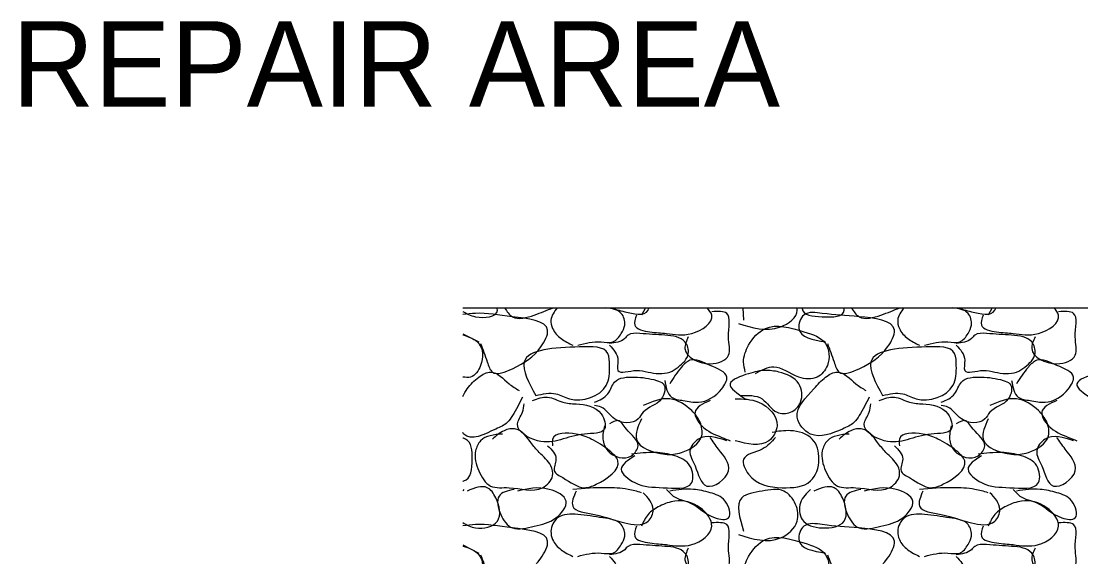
# Model space of a CAD drawing. Extents: x 2.92 to 10.05, y 1.3 to 10.63.
# Drawn here: x 3.291 to 4.036, y 6.374 to 6.75 of the extents above; entities that cross this region are included whole.
import ezdxf

# ---------------------------------------------------------------- set-up
doc = ezdxf.new("R2010")
doc.units = 0
for name, color, linetype in [('DETL-LINE', 7, 'Continuous'), ('DETL-NOTE', 7, 'Continuous'), ('DETL-PATT', 7, 'Continuous')]:
    doc.layers.add(name, color=color, linetype=linetype)

msp = doc.modelspace()

# ---------------------------------------------------------------- linework, layer by layer
at = {"layer": 'DETL-LINE'}
msp.add_line((3.60141, 6.54902), (7.87612, 6.54902), dxfattribs=at)
at = {"layer": 'DETL-PATT'}
for p, q in [((3.7298, 6.54902), (3.7269, 6.54392)), ((3.79824, 6.54902), (3.79867, 6.54039)), ((3.97333, 6.54902), (3.97043, 6.54392)), ((3.60141, 6.53078), (3.61278, 6.5251)), ((3.6022, 6.42157), (3.60141, 6.42051)), ((3.60141, 6.38255), (3.61278, 6.37686))]:
    msp.add_line(p, q, dxfattribs=at)
for points in [[(3.60141, 6.54651), (3.61043, 6.54275), (3.62573, 6.54745), (3.62561, 6.54902)], [(3.61396, 6.52392), (3.61867, 6.51098), (3.6222, 6.50392), (3.63631, 6.50627), (3.65631, 6.52157), (3.66102, 6.53333), (3.63631, 6.54275), (3.61043, 6.5451), (3.60141, 6.54427)], [(3.63082, 6.54902), (3.63631, 6.54275), (3.65161, 6.54392), (3.66486, 6.54902)], [(3.66769, 6.54902), (3.66337, 6.54039), (3.66455, 6.53451), (3.67043, 6.52745), (3.67867, 6.52275)], [(3.6822, 6.52275), (3.69867, 6.5251), (3.7069, 6.5251), (3.71278, 6.53098), (3.71514, 6.53686), (3.71278, 6.5451), (3.702, 6.54902)], [(3.70525, 6.54902), (3.71514, 6.54627), (3.73161, 6.54745), (3.73227, 6.54902)], [(3.72337, 6.54392), (3.7222, 6.53686), (3.73278, 6.53216), (3.74455, 6.53098), (3.7622, 6.53098), (3.77631, 6.54392), (3.77306, 6.54902)], [(3.75984, 6.52863), (3.75749, 6.52039), (3.77514, 6.5098), (3.78808, 6.51569), (3.78808, 6.52863), (3.7869, 6.5451), (3.77631, 6.54627)], [(3.79514, 6.53804), (3.82455, 6.53569), (3.83631, 6.54745), (3.83616, 6.54902)], [(3.85749, 6.52392), (3.8622, 6.51098), (3.86573, 6.50392), (3.87984, 6.50627), (3.89984, 6.52157), (3.90455, 6.53333), (3.87984, 6.54275), (3.85396, 6.5451), (3.84102, 6.54392), (3.83749, 6.53451), (3.85631, 6.5251)], [(3.8398, 6.54902), (3.83984, 6.54863), (3.85396, 6.54275), (3.86925, 6.54745), (3.86914, 6.54902)], [(3.87435, 6.54902), (3.87984, 6.54275), (3.89514, 6.54392), (3.90839, 6.54902)], [(3.91122, 6.54902), (3.9069, 6.54039), (3.90808, 6.53451), (3.91396, 6.52745), (3.9222, 6.52275)], [(3.92573, 6.52275), (3.9422, 6.5251), (3.95043, 6.5251), (3.95631, 6.53098), (3.95867, 6.53686), (3.95631, 6.5451), (3.94553, 6.54902)], [(3.94878, 6.54902), (3.95867, 6.54627), (3.97514, 6.54745), (3.9758, 6.54902)], [(3.9669, 6.54392), (3.96573, 6.53686), (3.97631, 6.53216), (3.98808, 6.53098), (4.00573, 6.53098), (4.01984, 6.54392), (4.01659, 6.54902)], [(4.00337, 6.52863), (4.00102, 6.52039), (4.01867, 6.5098), (4.03161, 6.51569), (4.03161, 6.52863), (4.03043, 6.5451), (4.01984, 6.54627)], [(3.79984, 6.50392), (3.79867, 6.51098), (3.8022, 6.52275), (3.81396, 6.53451), (3.84102, 6.53216), (3.85631, 6.52392), (3.85749, 6.50863), (3.85043, 6.50039), (3.83749, 6.50039), (3.81984, 6.50745), (3.8069, 6.50275)], [(3.60141, 6.53004), (3.61278, 6.52392), (3.61396, 6.50863), (3.6069, 6.50039), (3.60141, 6.50039)], [(3.70455, 6.52275), (3.71043, 6.51216), (3.71043, 6.5051), (3.72337, 6.5051), (3.73161, 6.50392), (3.7469, 6.50392), (3.75278, 6.50745), (3.75984, 6.51686), (3.75749, 6.5251), (3.75161, 6.52863), (3.74337, 6.5298), (3.72573, 6.53098), (3.71749, 6.5298), (3.71514, 6.52745), (3.70455, 6.52392)], [(3.94808, 6.52275), (3.95396, 6.51216), (3.95396, 6.5051), (3.9669, 6.5051), (3.97514, 6.50392), (3.99043, 6.50392), (3.99631, 6.50745), (4.00337, 6.51686), (4.00102, 6.5251), (3.99514, 6.52863), (3.9869, 6.5298), (3.96925, 6.53098), (3.96102, 6.5298), (3.95867, 6.52745), (3.94808, 6.52392)], [(3.65278, 6.48745), (3.64455, 6.51098), (3.68337, 6.52157), (3.70337, 6.51686), (3.70455, 6.50863), (3.7022, 6.49451), (3.67631, 6.4851), (3.6669, 6.48863), (3.65278, 6.48745)], [(3.89631, 6.48745), (3.88808, 6.51098), (3.9269, 6.52157), (3.9469, 6.51686), (3.94808, 6.50863), (3.94573, 6.49451), (3.91984, 6.4851), (3.91043, 6.48863), (3.89631, 6.48745)], [(3.74337, 6.49804), (3.74808, 6.48627), (3.75631, 6.48392), (3.7669, 6.48275), (3.78337, 6.49216), (3.7869, 6.50039), (3.77514, 6.50863), (3.76102, 6.51216), (3.75514, 6.50745), (3.7469, 6.49569)], [(3.9869, 6.49804), (3.99161, 6.48627), (3.99984, 6.48392), (4.01043, 6.48275), (4.0269, 6.49216), (4.03043, 6.50039), (4.01867, 6.50863), (4.00455, 6.51216), (3.99867, 6.50745), (3.99043, 6.49569)], [(3.79631, 6.48745), (3.81161, 6.4851), (3.8222, 6.47569), (3.83161, 6.47569), (3.83867, 6.48275), (3.83749, 6.49569), (3.82337, 6.50392), (3.81396, 6.5051), (3.8022, 6.50275), (3.78925, 6.49569), (3.79984, 6.4851)], [(4.03984, 6.48745), (4.05514, 6.4851), (4.06573, 6.47569), (4.07514, 6.47569), (4.0822, 6.48275), (4.08102, 6.49569), (4.0669, 6.50392), (4.05749, 6.5051), (4.04573, 6.50275), (4.03278, 6.49569), (4.04337, 6.4851)], [(3.60141, 6.48682), (3.60455, 6.49216), (3.61278, 6.50039), (3.62102, 6.50392), (3.63396, 6.49569), (3.64102, 6.49098)], [(3.69396, 6.48275), (3.70337, 6.48863), (3.70808, 6.49686), (3.7222, 6.50039), (3.73749, 6.49804), (3.7422, 6.49569), (3.74102, 6.4851), (3.72808, 6.47569), (3.72455, 6.47098), (3.70808, 6.47098), (3.69867, 6.47922), (3.69396, 6.48039)], [(3.8869, 6.48627), (3.87984, 6.47333), (3.87631, 6.46863), (3.86808, 6.46392), (3.84573, 6.46039), (3.83631, 6.47216), (3.84808, 6.49216), (3.85631, 6.50039), (3.86455, 6.50392), (3.87749, 6.49569), (3.88455, 6.49098)], [(3.93749, 6.48275), (3.9469, 6.48863), (3.95161, 6.49686), (3.96573, 6.50039), (3.98102, 6.49804), (3.98573, 6.49569), (3.98455, 6.4851), (3.97161, 6.47569), (3.96808, 6.47098), (3.95161, 6.47098), (3.9422, 6.47922), (3.93749, 6.48039)], [(3.64337, 6.48627), (3.63631, 6.47333), (3.63278, 6.46863), (3.62455, 6.46392), (3.6022, 6.46039), (3.60141, 6.46137)], [(3.65043, 6.48392), (3.66102, 6.48627), (3.67161, 6.48275), (3.68102, 6.48157), (3.69867, 6.47451), (3.70102, 6.46392), (3.6869, 6.46039), (3.65396, 6.45569), (3.63984, 6.46745), (3.64337, 6.47569), (3.64455, 6.48157)], [(3.7269, 6.47098), (3.72337, 6.45686), (3.74337, 6.44627), (3.75514, 6.44745), (3.76925, 6.45922), (3.76808, 6.46863), (3.7622, 6.47686), (3.7469, 6.4851), (3.72808, 6.48039)], [(3.77514, 6.48392), (3.76455, 6.47569), (3.76925, 6.46627), (3.78337, 6.45804), (3.78925, 6.45569)], [(3.79278, 6.4851), (3.80925, 6.48275), (3.8222, 6.46627), (3.81631, 6.45569), (3.79278, 6.45569)], [(3.89396, 6.48392), (3.90455, 6.48627), (3.91514, 6.48275), (3.92455, 6.48157), (3.9422, 6.47451), (3.94455, 6.46392), (3.93043, 6.46039), (3.89749, 6.45569), (3.88337, 6.46745), (3.8869, 6.47569), (3.88808, 6.48157)], [(3.97043, 6.47098), (3.9669, 6.45686), (3.9869, 6.44627), (3.99867, 6.44745), (4.01278, 6.45922), (4.01161, 6.46863), (4.00573, 6.47686), (3.99043, 6.4851), (3.97161, 6.48039)], [(4.01867, 6.48392), (4.00808, 6.47569), (4.01278, 6.46627), (4.0269, 6.45804), (4.03278, 6.45569)], [(3.70102, 6.46627), (3.69984, 6.45686), (3.70337, 6.44863), (3.71984, 6.4451), (3.72455, 6.45216), (3.71631, 6.46392), (3.71043, 6.4698), (3.70455, 6.46745)], [(3.94455, 6.46627), (3.94337, 6.45686), (3.9469, 6.44863), (3.96337, 6.4451), (3.96808, 6.45216), (3.95984, 6.46392), (3.95396, 6.4698), (3.94808, 6.46745)], [(3.62925, 6.46039), (3.61396, 6.45569), (3.61043, 6.44863), (3.61278, 6.43451), (3.62102, 6.42392), (3.63396, 6.42275), (3.65749, 6.42275), (3.66455, 6.43098), (3.66337, 6.43804), (3.65514, 6.44745), (3.64925, 6.45451), (3.63867, 6.46392), (3.63043, 6.46275), (3.6222, 6.45686)], [(3.66102, 6.45216), (3.6669, 6.44275), (3.66573, 6.43451), (3.67161, 6.4298), (3.6869, 6.42275), (3.69514, 6.4251), (3.71043, 6.44157), (3.70455, 6.44863), (3.69161, 6.45686), (3.68102, 6.46039), (3.66455, 6.45686), (3.66455, 6.45216)], [(3.7869, 6.45569), (3.7669, 6.45686), (3.76102, 6.44863), (3.76455, 6.43804), (3.77278, 6.42392), (3.78808, 6.43451), (3.78102, 6.4498), (3.77514, 6.45804)], [(3.82102, 6.45804), (3.81161, 6.4498), (3.79867, 6.44275), (3.8022, 6.43216), (3.82573, 6.42275), (3.84573, 6.42745), (3.85161, 6.44275), (3.8469, 6.45686), (3.83161, 6.46275), (3.81867, 6.46157)], [(3.87278, 6.46039), (3.85749, 6.45569), (3.85396, 6.44863), (3.85631, 6.43451), (3.86455, 6.42392), (3.87749, 6.42275), (3.90102, 6.42275), (3.90808, 6.43098), (3.9069, 6.43804), (3.89867, 6.44745), (3.89278, 6.45451), (3.8822, 6.46392), (3.87396, 6.46275), (3.86573, 6.45686)], [(3.90455, 6.45216), (3.91043, 6.44275), (3.90925, 6.43451), (3.91514, 6.4298), (3.93043, 6.42275), (3.93867, 6.4251), (3.95396, 6.44157), (3.94808, 6.44863), (3.93514, 6.45686), (3.92455, 6.46039), (3.90808, 6.45686), (3.90808, 6.45216)], [(4.03043, 6.45569), (4.01043, 6.45686), (4.00455, 6.44863), (4.00808, 6.43804), (4.01631, 6.42392), (4.03161, 6.43451), (4.02455, 6.4498), (4.01867, 6.45804)], [(3.60141, 6.42725), (3.6022, 6.42745), (3.60808, 6.44275), (3.60337, 6.45686), (3.60141, 6.45761)], [(3.7222, 6.4451), (3.71278, 6.43569), (3.7222, 6.42627), (3.7422, 6.42275), (3.7622, 6.42627), (3.76102, 6.43804), (3.75043, 6.4451), (3.73631, 6.44745), (3.71984, 6.44627)], [(3.96573, 6.4451), (3.95631, 6.43569), (3.96573, 6.42627), (3.98573, 6.42275), (4.00573, 6.42627), (4.00455, 6.43804), (3.99396, 6.4451), (3.97984, 6.44745), (3.96337, 6.44627)], [(3.60141, 6.39827), (3.61043, 6.39451), (3.62573, 6.39922), (3.62455, 6.41569), (3.61867, 6.42275), (3.60455, 6.42039)], [(3.63749, 6.42157), (3.6269, 6.41686), (3.62808, 6.40392), (3.63631, 6.39451), (3.65161, 6.39569), (3.6669, 6.40157), (3.67396, 6.41333), (3.6622, 6.42157), (3.63984, 6.42039)], [(3.7269, 6.41922), (3.71749, 6.42157), (3.7022, 6.42275), (3.67867, 6.42157)], [(3.84573, 6.42157), (3.83867, 6.41216), (3.83984, 6.40039), (3.85396, 6.39451), (3.86925, 6.39922), (3.86808, 6.41569), (3.8622, 6.42275), (3.84808, 6.42039)], [(3.88102, 6.42157), (3.87043, 6.41686), (3.87161, 6.40392), (3.87984, 6.39451), (3.89514, 6.39569), (3.91043, 6.40157), (3.91749, 6.41333), (3.90573, 6.42157), (3.88337, 6.42039)], [(3.97043, 6.41922), (3.96102, 6.42157), (3.94573, 6.42275), (3.9222, 6.42157)], [(3.68102, 6.42039), (3.67867, 6.4098), (3.69396, 6.40392), (3.71514, 6.39804), (3.73161, 6.39922), (3.73514, 6.40745), (3.72808, 6.41922)], [(3.74455, 6.42157), (3.74925, 6.41686), (3.76102, 6.41216), (3.77867, 6.40157), (3.78808, 6.40157), (3.78573, 6.41333), (3.77514, 6.41922), (3.76337, 6.42157), (3.7469, 6.42039)], [(3.79514, 6.3898), (3.82455, 6.38745), (3.83631, 6.39922), (3.83514, 6.41098), (3.8269, 6.42039), (3.81161, 6.42039), (3.79749, 6.41569), (3.79867, 6.39216)], [(3.92455, 6.42039), (3.9222, 6.4098), (3.93749, 6.40392), (3.95867, 6.39804), (3.97514, 6.39922), (3.97867, 6.40745), (3.97161, 6.41922)], [(3.98808, 6.42157), (3.99278, 6.41686), (4.00455, 6.41216), (4.0222, 6.40157), (4.03161, 6.40157), (4.02925, 6.41333), (4.01867, 6.41922), (4.0069, 6.42157), (3.99043, 6.42039)], [(3.72337, 6.39569), (3.7222, 6.38863), (3.73278, 6.38392), (3.74455, 6.38275), (3.7622, 6.38275), (3.77631, 6.39569), (3.76808, 6.40863), (3.75043, 6.41333), (3.73984, 6.4098), (3.73161, 6.40392), (3.7269, 6.39569)], [(3.9669, 6.39569), (3.96573, 6.38863), (3.97631, 6.38392), (3.98808, 6.38275), (4.00573, 6.38275), (4.01984, 6.39569), (4.01161, 6.40863), (3.99396, 6.41333), (3.98337, 6.4098), (3.97514, 6.40392), (3.97043, 6.39569)], [(3.6822, 6.37451), (3.69867, 6.37686), (3.7069, 6.37686), (3.71278, 6.38275), (3.71514, 6.38863), (3.71278, 6.39686), (3.69984, 6.40157), (3.6822, 6.40392), (3.66808, 6.40157), (3.66337, 6.39216), (3.66455, 6.38627), (3.67043, 6.37922), (3.67867, 6.37451)], [(3.92573, 6.37451), (3.9422, 6.37686), (3.95043, 6.37686), (3.95631, 6.38275), (3.95867, 6.38863), (3.95631, 6.39686), (3.94337, 6.40157), (3.92573, 6.40392), (3.91161, 6.40157), (3.9069, 6.39216), (3.90808, 6.38627), (3.91396, 6.37922), (3.9222, 6.37451)], [(3.61396, 6.37569), (3.61867, 6.36275), (3.6222, 6.35569), (3.63631, 6.35804), (3.65631, 6.37333), (3.66102, 6.3851), (3.63631, 6.39451), (3.61043, 6.39686), (3.60141, 6.39604)], [(3.75984, 6.38039), (3.75749, 6.37216), (3.77514, 6.36157), (3.78808, 6.36745), (3.78808, 6.38039), (3.7869, 6.39686), (3.77631, 6.39804)], [(3.85749, 6.37569), (3.8622, 6.36275), (3.86573, 6.35569), (3.87984, 6.35804), (3.89984, 6.37333), (3.90455, 6.3851), (3.87984, 6.39451), (3.85396, 6.39686), (3.84102, 6.39569), (3.83749, 6.38627), (3.85631, 6.37686)], [(4.00337, 6.38039), (4.00102, 6.37216), (4.01867, 6.36157), (4.03161, 6.36745), (4.03161, 6.38039), (4.03043, 6.39686), (4.01984, 6.39804)], [(3.79984, 6.35569), (3.79867, 6.36275), (3.8022, 6.37451), (3.81396, 6.38627), (3.84102, 6.38392), (3.85631, 6.37569), (3.85749, 6.36039), (3.85043, 6.35216), (3.83749, 6.35216), (3.81984, 6.35922), (3.8069, 6.35451)], [(3.60141, 6.3818), (3.61278, 6.37569), (3.61396, 6.36039), (3.6069, 6.35216), (3.60141, 6.35216)], [(3.70455, 6.37451), (3.71043, 6.36392), (3.71043, 6.35686), (3.72337, 6.35686), (3.73161, 6.35569), (3.7469, 6.35569), (3.75278, 6.35922), (3.75984, 6.36863), (3.75749, 6.37686), (3.75161, 6.38039), (3.74337, 6.38157), (3.72573, 6.38275), (3.71749, 6.38157), (3.71514, 6.37922), (3.70455, 6.37569)], [(3.94808, 6.37451), (3.95396, 6.36392), (3.95396, 6.35686), (3.9669, 6.35686), (3.97514, 6.35569), (3.99043, 6.35569), (3.99631, 6.35922), (4.00337, 6.36863), (4.00102, 6.37686), (3.99514, 6.38039), (3.9869, 6.38157), (3.96925, 6.38275), (3.96102, 6.38157), (3.95867, 6.37922), (3.94808, 6.37569)]]:
    msp.add_spline(points, degree=3, dxfattribs=at)

# ---------------------------------------------------------------- texts
at = {"layer": 'DETL-NOTE'}
msp.add_text('REPAIR AREA', height=0.06, dxfattribs=at).set_placement((3.28471, 6.6902))

doc.saveas('drawing.dxf')
